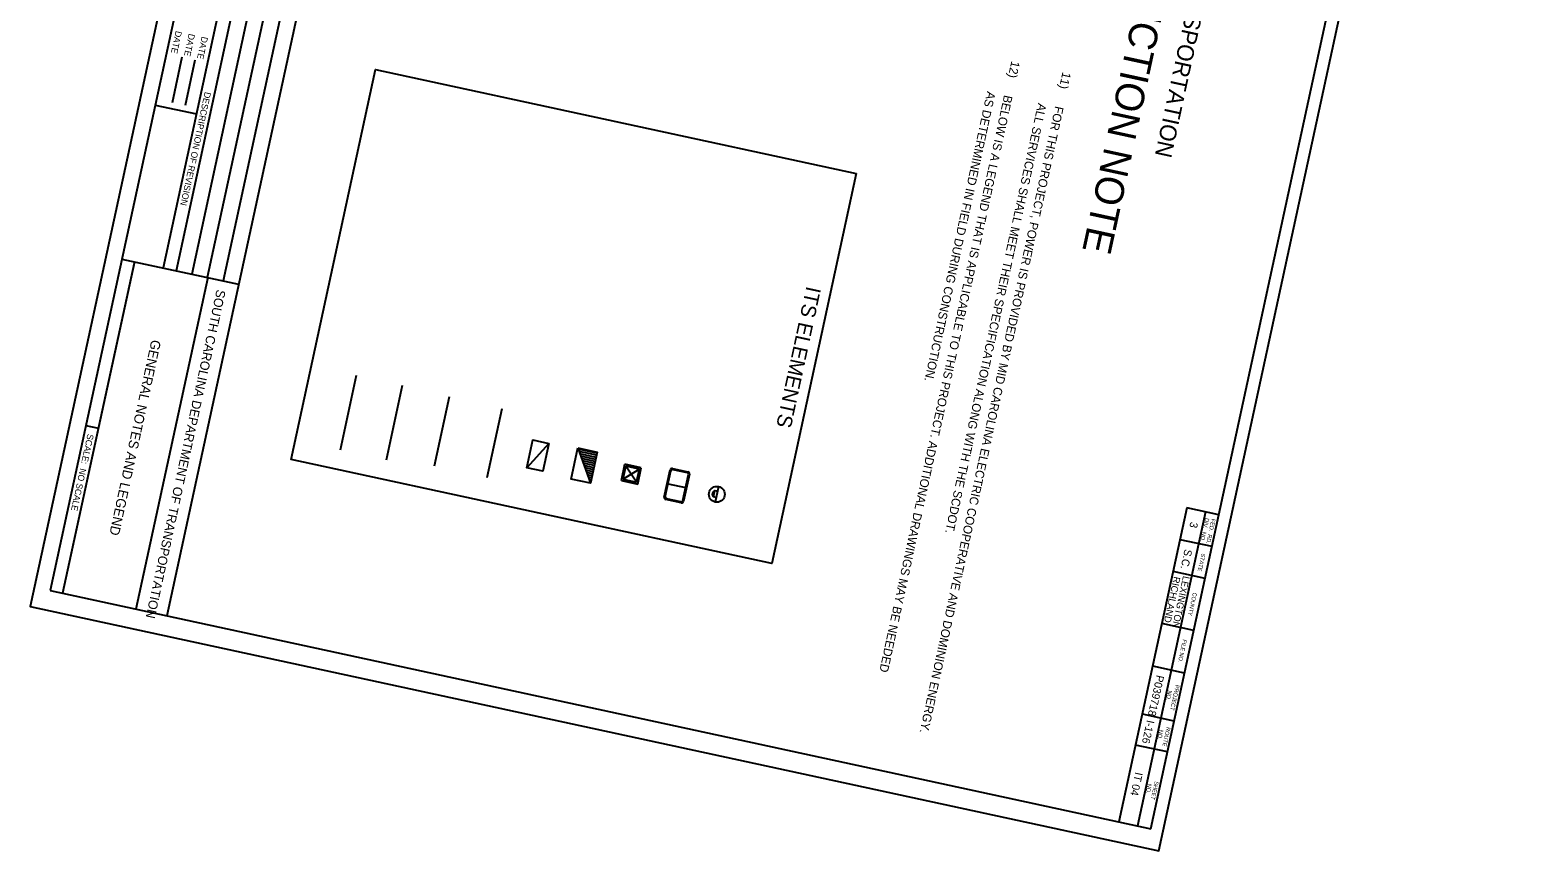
# Model space of a CAD drawing. Extents: x 1897817 to 2050613, y 442539 to 798440.
# Drawn here: x 1976813 to 1979013, y 782132 to 783329 of the extents above; entities that cross this region are included whole.
import ezdxf

# ---------------------------------------------------------------- set-up
doc = ezdxf.new("R2010")
doc.units = 0
for name, color, linetype in [('Default', 7, 'Continuous'), ('RD_SHT_Bndy', 7, 'Continuous'), ('RD_SHT_IplotShp', 7, 'Continuous'), ('RD_SHT_TX', 7, 'Continuous')]:
    doc.layers.add(name, color=color, linetype=linetype)

msp = doc.modelspace()

# ---------------------------------------------------------------- linework, layer by layer
at = {"layer": 'Default'}
for p, q in [((1977132.8, 783562), (1977007.3, 782982.1)), ((1977151.8, 783557.9), (1977026.2, 782978)), ((1977174.5, 783553), (1977049.1, 782973.1)), ((1977197.3, 783548), (1977071.8, 782968.2)), ((1977220.2, 783543.1), (1977094.7, 782963.3)), ((1977034.8, 783289.4), (1977020.5, 783223.2)), ((1977053.8, 783285.3), (1977039.5, 783219.1)), ((1976995.8, 783219.7), (1977055.9, 783206.7)), ((1976947.2, 782995.1), (1977117.5, 782958.3)), ((1976947.2, 782995.1), (1977117.5, 782958.3)), ((1976947.2, 782995.1), (1977117.5, 782958.3)), ((1976947.2, 782995.1), (1977117.5, 782958.3)), ((1977288.9, 782824.9), (1977265.4, 782716.2)), ((1977356, 782810.4), (1977332.5, 782701.7)), ((1977569.9, 782726.1), (1977538, 782690.4)), ((1977612.2, 782719.4), (1977630.7, 782668)), ((1977640.1, 782711.7), (1977612.8, 782717.7)), ((1977639.5, 782708.7), (1977614, 782714.2)), ((1977638.8, 782705.7), (1977615.3, 782710.8)), ((1977638.2, 782702.7), (1977616.5, 782707.4)), ((1977637.5, 782699.7), (1977617.7, 782704)), ((1977636.9, 782696.7), (1977619, 782700.5)), ((1977636.2, 782693.7), (1977620.2, 782697.1)), ((1977635.6, 782690.6), (1977621.4, 782693.7)), ((1977634.9, 782687.6), (1977622.7, 782690.3)), ((1977675.7, 782671.8), (1977680.9, 782695.6)), ((1977678.4, 782673.7), (1977682.5, 782692.7)), ((1977704.7, 782690.5), (1977680.9, 782695.6)), ((1977697.9, 782669.5), (1977682.5, 782692.7)), ((1977702, 782688.5), (1977682.5, 782692.7)), ((1977699.6, 782666.6), (1977704.7, 782690.5)), ((1977634.3, 782684.6), (1977623.9, 782686.9)), ((1977633.6, 782681.6), (1977625.1, 782683.4)), ((1977632.9, 782678.6), (1977626.3, 782680)), ((1977632.3, 782675.6), (1977627.6, 782676.6)), ((1977631.6, 782672.5), (1977628.8, 782673.2)), ((1977631, 782669.5), (1977630, 782669.7)), ((1977675.7, 782671.8), (1977699.6, 782666.6)), ((1977702, 782688.5), (1977678.4, 782673.7)), ((1977678.4, 782673.7), (1977697.9, 782669.5)), ((1977697.9, 782669.5), (1977702, 782688.5)), ((1977743.9, 782667.2), (1977769.4, 782661.7)), ((1977817.5, 782663.1), (1977812.6, 782640.5)), ((1978500.8, 782632), (1978401.6, 782173.8)), ((1978527.9, 782626.1), (1978428.7, 782168)), ((1978547.3, 782622), (1978500.8, 782632)), ((1978537.3, 782575.5), (1978490.8, 782585.5)), ((1978527.2, 782529.1), (1978480.8, 782539.2)), ((1978510.8, 782453.3), (1978464.3, 782463.3)), ((1978497.2, 782390.8), (1978450.8, 782400.9)), ((1978482.1, 782321), (1978435.7, 782331)), ((1978472.4, 782276.1), (1978425.9, 782286))]:
    msp.add_line(p, q, dxfattribs=at)
for points in [[(1978018.3, 783119.7), (1977895.2, 782550.8), (1977194, 782702.6), (1977317.1, 783271.5)], [(1977569.9, 782726.1), (1977561.1, 782685.4), (1977538, 782690.4), (1977546.8, 782731.1)], [(1977612.2, 782719.4), (1977640.5, 782713.2), (1977630.7, 782668), (1977602.4, 782674.1)], [(1977816, 782656.3), (1977814, 782647), (1977809.9, 782647.9), (1977811.9, 782657.2)]]:
    msp.add_lwpolyline(points, close=True, dxfattribs=at)
for points in [[(1977424.6, 782794), (1977402.7, 782692.9)], [(1977501.5, 782776.7), (1977479.6, 782675.7)], [(1977750.3, 782689.5), (1977772.9, 782684.6)], [(1977738.3, 782647.7), (1977746.8, 782687.3)], [(1977739.8, 782648.2), (1977748.1, 782686.2)], [(1977750.8, 782688), (1977771.8, 782683.5)], [(1977765.3, 782642.7), (1977773.5, 782680.7)], [(1977775.1, 782681.2), (1977766.5, 782641.6)], [(1977762.5, 782640.9), (1977741.6, 782645.4)], [(1977763.1, 782639.4), (1977740.5, 782644.3)]]:
    msp.add_lwpolyline(points, dxfattribs=at)
msp.add_circle((1977815, 782651.8), 11.6, dxfattribs=at)
for centre, radius, start, end in [((1977749.7, 782686.7), 2.89, 77.7861, 167.7861), ((1977750.3, 782685.7), 2.31, 77.7861, 167.7861), ((1977771.3, 782681.2), 2.31, 347.7861, 77.7861), ((1977772.3, 782681.8), 2.89, 347.7861, 77.7861), ((1977741.1, 782647.1), 2.89, 167.7861, 257.7861), ((1977742.1, 782647.7), 2.31, 167.7861, 257.7861), ((1977814.1, 782651.9), 5.74, 111.6411, 223.9311), ((1977763, 782643.1), 2.31, 257.7861, 347.7861), ((1977763.7, 782642.2), 2.89, 257.7861, 347.7861)]:
    msp.add_arc(centre, radius, start, end, dxfattribs=at)
at = {"layer": 'RD_SHT_Bndy'}
for p, q in [((1977385.5, 785019.6), (1976842.5, 782511.3)), ((1978448.1, 782163.8), (1978991.1, 784672.1)), ((1977388.8, 784211.8), (1977012.8, 782474.5)), ((1976965.5, 782991.2), (1976860.7, 782507.4)), ((1976965, 782988.9), (1976860.7, 782507.4)), ((1977072.3, 782968.1), (1976967.6, 782484.2)), ((1977072.4, 782968.1), (1976967.6, 782484.2)), ((1976894.7, 782752.1), (1976912.9, 782748.1)), ((1976894.7, 782752.1), (1976912.9, 782748.1)), ((1976842.5, 782511.3), (1976842.6, 782511.3)), ((1976842.6, 782511.3), (1978448.1, 782163.8))]:
    msp.add_line(p, q, dxfattribs=at)
at = {"layer": 'RD_SHT_IplotShp'}
msp.add_lwpolyline([(1977366.1, 785041.7), (1976813.4, 782488), (1978459.8, 782131.6), (1979012.6, 784685.3)], close=True, dxfattribs=at)

# ---------------------------------------------------------------- texts
at = {"layer": 'Default'}
for s, height, rotation, p in [('GENERAL CONSTRUCTION NOTE', 41.774, 257.7861, (1978539, 783890.8)), ('DEPARTMENT OF TRANSPORTATION', 24.361, 257.7861, (1978578.3, 783721.2)), ('DATE   ', 9.33, 257.7859, (1977025.7, 783328.5)), ('DATE   ', 9.33, 257.7859, (1977044.8, 783324.5)), ('DATE   ', 9.33, 257.7859, (1977063.7, 783320.3)), ('12)', 12.71, 257.7861, (1978244.8, 783284.7)), ('11)', 12.71, 257.7861, (1978319.3, 783268.6)), ('AS DETERMINED IN FIELD DURING CONSTRUCTION.', 12.706, 257.7861, (1978209.2, 783240.4)), ('DESCRIPTION OF REVISION', 9.334, 257.7859, (1977068.1, 783239.5)), ('BELOW IS A LEGEND THAT IS APPLICABLE TO THIS PROJECT. ADDITIONAL DRAWINGS MAY BE NEEDED ', 12.706, 257.7861, (1978234.1, 783235)), ('FOR THIS PROJECT, POWER IS PROVIDED BY MID CAROLINA ELECTRIC COOPERATIVE AND DOMINION ENERGY.', 12.706, 257.7861, (1978308.6, 783218.9)), ('           ALL SERVICES SHALL MEET THEIR SPECIFICATION ALONG WITH THE SCDOT.', 12.706, 257.7861, (1978294.5, 783274)), ('ITS ELEMENTS', 21.689, 257.7861, (1977945.9, 782956.3)), ('3', 11.3, 257.786, (1978506, 782612.2)), ('DIV.  NO.', 5.93, 257.7858, (1978527.6, 782617.6)), ('FED.  RD.', 5.93, 257.7858, (1978536.7, 782616.6)), ('S.C.', 11.32, 257.786, (1978497.5, 782572.5)), ('STATE', 5.93, 257.786, (1978521.9, 782565.9)), ('RICHLAND', 10, 257.786, (1978481.6, 782532.5)), ('LEXINGTON', 10, 257.786, (1978495.2, 782533.3)), ('COUNTY', 5.93, 257.786, (1978509.6, 782508.9)), ('FILE NO.', 5.93, 257.786, (1978494.9, 782440.6)), ('P039718', 11.32, 257.786, (1978456.5, 782388.7)), ('NO.', 5.93, 257.7857, (1978473.2, 782366)), ('PROJECT', 5.93, 257.7857, (1978484.2, 782374.3)), ('I-126', 11.32, 257.786, (1978442.3, 782323.1)), ('NO.', 5.93, 257.7857, (1978460.7, 782308.6)), ('ROUTE', 5.93, 257.7857, (1978471, 782312.6)), ('IT 04', 11.32, 257.786, (1978425.4, 782247.1)), ('NO.', 5.93, 257.7857, (1978443.8, 782230)), ('SHEET', 5.93, 257.7857, (1978453.8, 782233.5))]:
    msp.add_text(s, height=height, rotation=rotation, dxfattribs=at).set_placement(p)
at = {"layer": 'RD_SHT_TX'}
for s, height, rotation, p in [('SOUTH CAROLINA DEPARTMENT OF TRANSPORTATION', 13.46, 257.7861, (1977085.5, 782951.3)), ('GENERAL NOTES AND LEGEND', 14.252, 257.7862, (1976990.4, 782878.1)), ('SCALE:  NO SCALE', 9.326, 257.7861, (1976897.1, 782740.4))]:
    msp.add_text(s, height=height, rotation=rotation, dxfattribs=at).set_placement(p)

doc.saveas('drawing.dxf')
